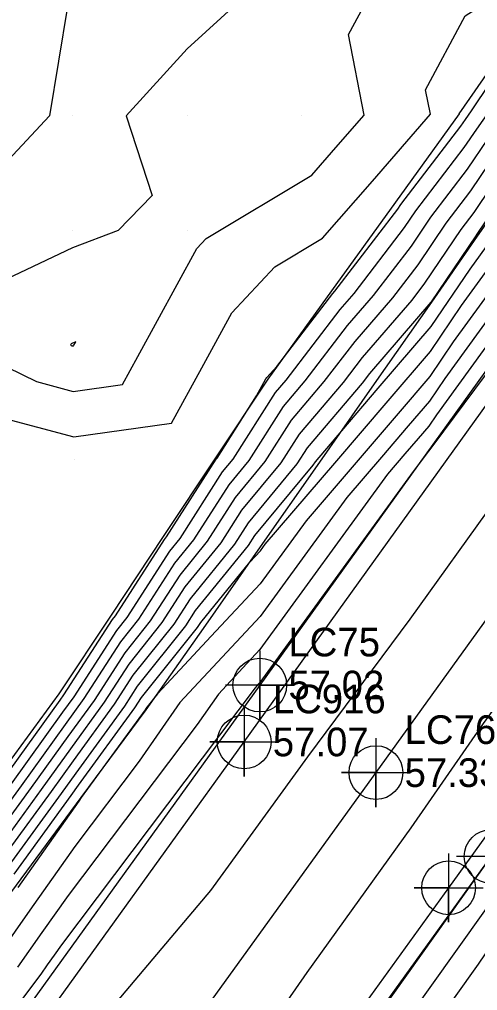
# Model space of a CAD drawing. Extents: x 2188792 to 2191981, y 386090 to 389710.
# Drawn here: x 2189815.5 to 2189855.4, y 387193.8 to 387278.5 of the extents above; entities that cross this region are included whole.
import ezdxf

# ---------------------------------------------------------------- set-up
doc = ezdxf.new("R2010")
doc.units = 0
for name, color, linetype in [('DTM Contours Major', 7, 'Continuous'), ('DTM Contours Minor', 7, 'Continuous'), ('Exist DTM QL2 LIDAR Elevation Point', 7, 'Continuous'), ('Exist Roads EOP', 7, 'Continuous'), ('Exist Roads EOP Cogo Elevation', 7, 'Continuous'), ('Exist Roads EOP Cogo Number', 7, 'Continuous'), ('Exist Roads EOP Cogo Point CELL', 7, 'Continuous'), ('Exist Roads EOT', 7, 'Continuous'), ('Exist Roads EOT Cogo Elevation', 7, 'Continuous'), ('Exist Roads EOT Cogo Number', 7, 'Continuous'), ('Exist Roads EOT Cogo Point CELL', 7, 'Continuous'), ('PH Exist DTM Breakline', 7, 'Continuous')]:
    doc.layers.add(name, color=color, linetype=linetype)

msp = doc.modelspace()

# ---------------------------------------------------------------- linework, layer by layer
at = {"layer": 'DTM Contours Major'}
for points in [[(2189839.476, 387181.412), (2189856.598, 387205.434), (2189856.62, 387205.466), (2189856.64, 387205.496), (2189856.659, 387205.525), (2189858.223, 387207.732), (2189869.834, 387224.619), (2189877.249, 387235.156), (2189886.017, 387247.794), (2189890.656, 387253.898), (2189892.445, 387256.247), (2189909.424, 387278.537), (2189910.292, 387279.677), (2189910.315, 387279.709), (2189911.35, 387281.066), (2189927.816, 387303.457), (2189927.931, 387303.631), (2189928.041, 387303.798), (2189928.147, 387303.957), (2189928.3, 387304.131), (2189939.5, 387319.43), (2189939.713, 387319.861), (2189939.829, 387320.314), (2189949.954, 387334.279)], [(2189889.131, 387294.16), (2189875.837, 387275.244), (2189873.402, 387271.521), (2189871.117, 387268.163), (2189868.023, 387263.523), (2189851.528, 387241.376), (2189851.153, 387240.864), (2189849.827, 387239.091), (2189836.429, 387220.687), (2189836.321, 387220.571), (2189836.166, 387220.405), (2189836.033, 387220.214), (2189819.116, 387197.803), (2189818.476, 387196.893), (2189817.877, 387196.042), (2189817.316, 387195.246), (2189805.405, 387179.378)], [(2189814.781, 387205.028), (2189819.114, 387210.993), (2189820.392, 387212.776), (2189824.645, 387218.631), (2189825.754, 387220.352), (2189829.968, 387225.621), (2189830.826, 387226.958), (2189835.436, 387232.628), (2189835.992, 387233.498), (2189841.102, 387239.658), (2189841.287, 387239.949), (2189843.591, 387242.658), (2189846.764, 387246.355), (2189851.385, 387251.738), (2189854.777, 387256.754), (2189857.49, 387260.492), (2189860.766, 387265.355), (2189865.205, 387271.534), (2189865.782, 387272.354), (2189870.049, 387278.295), (2189874.071, 387283.895)], [(2189814.771, 387211.853), (2189819.239, 387218.082), (2189820.225, 387219.44), (2189823.946, 387225.213), (2189824.855, 387226.349), (2189828.568, 387232.132), (2189829.484, 387233.259), (2189833.187, 387239.053), (2189834.112, 387240.169), (2189837.802, 387245.976), (2189838.739, 387247.078), (2189843.449, 387253.234), (2189844.661, 387254.641), (2189849.066, 387260.374), (2189850.055, 387261.845), (2189854.272, 387267.354), (2189855.357, 387268.963), (2189856.833, 387271.018), (2189860.8, 387276.948), (2189862.222, 387278.923)]]:
    msp.add_lwpolyline(points, dxfattribs=at)
at = {"layer": 'DTM Contours Minor'}
for points in [[(2189806.103, 387171.079), (2189818.83, 387185.769), (2189823.977, 387192.841), (2189832.146, 387202.524), (2189840.636, 387214.199), (2189849.542, 387226.21), (2189857.019, 387236.627), (2189863.862, 387245.866), (2189872.906, 387258.466), (2189874.441, 387260.833), (2189883.298, 387274.48), (2189889.961, 387284.755), (2189894.836, 387292.266), (2189899.699, 387299.764), (2189911.601, 387317.434), (2189912.049, 387318.099), (2189914.929, 387322.013), (2189928.336, 387339.246)], [(2189813.858, 387243.807), (2189820.216, 387242.114), (2189828.739, 387243.302), (2189831.378, 387248.153), (2189833.988, 387252.937), (2189837.728, 387256.941), (2189841.913, 387259.442), (2189846.252, 387264.442), (2189851.314, 387270.276), (2189850.901, 387272.402), (2189854.354, 387278.869), (2189857.509, 387280.879), (2189861.388, 387287.422), (2189863.782, 387290.182), (2189867.521, 387296.313), (2189870.901, 387301.854), (2189870.566, 387305.397), (2189874.896, 387306.987), (2189878.866, 387313.349), (2189882.188, 387319.115), (2189885.105, 387322.219), (2189888.384, 387327.734)], [(2189830.091, 387327.202), (2189821.116, 387320.135), (2189820.905, 387319.321), (2189820.191, 387310.134), (2189827.038, 387307.081), (2189829.651, 387300.133), (2189830.091, 387297.292), (2189831.409, 387290.132), (2189830.091, 387286.609), (2189826.983, 387283.24), (2189820.09, 387280.72), (2189818.925, 387281.297), (2189817.626, 387280.131), (2189819.642, 387279.683), (2189818.075, 387270.13), (2189810.09, 387261.582)], [(2189937.835, 387325.802), (2189928.451, 387313.821), (2189924.705, 387308.455), (2189912.794, 387292.052), (2189906.641, 387284.303), (2189906.065, 387283.51), (2189895.672, 387270.72), (2189887.112, 387259.916), (2189885.216, 387257.522), (2189881.384, 387252.787), (2189871.553, 387239.191), (2189863.95, 387228.232), (2189855.914, 387217.121), (2189849.603, 387208.007), (2189840.533, 387195.387), (2189832.223, 387183.387), (2189825.819, 387174.474), (2189818.869, 387164.423), (2189809.4, 387152.406)], [(2189810.442, 387250.128), (2189816.943, 387246.936), (2189820.154, 387246.081), (2189824.458, 387246.681), (2189825.791, 387249.131), (2189830.938, 387258.566), (2189831.751, 387259.436), (2189840.975, 387264.949), (2189843.078, 387267.373), (2189845.532, 387270.201), (2189844.168, 387277.217), (2189845.47, 387279.656), (2189854.089, 387285.146), (2189856.18, 387288.672), (2189861.898, 387295.265), (2189863.728, 387298.264), (2189865.381, 387300.975), (2189864.714, 387308.045), (2189873.352, 387311.215), (2189876.045, 387315.531), (2189878.299, 387319.443), (2189883.416, 387324.889)], [(2189855.326, 387325.368), (2189854.148, 387320.135), (2189852.181, 387312.222), (2189854.893, 387310.134), (2189854.413, 387305.814), (2189850.093, 387306.667), (2189846.951, 387300.133), (2189847.286, 387292.939), (2189840.092, 387292.165), (2189835.482, 387294.742), (2189836.331, 387290.132), (2189834.084, 387284.123), (2189834.654, 387280.131), (2189830.091, 387275.989), (2189824.774, 387270.13), (2189827.041, 387263.18), (2189824.072, 387260.129), (2189820.09, 387258.603), (2189814.336, 387255.883)], [(2189849.089, 387187.083), (2189855.514, 387196.097), (2189858.561, 387200.607), (2189861.481, 387204.929), (2189864.282, 387209.076), (2189870.405, 387217.719), (2189872.925, 387221.801), (2189874.972, 387225.117), (2189876.668, 387227.865), (2189886.895, 387242.237), (2189888.817, 387245.23), (2189890.642, 387248.071), (2189892.222, 387250.529), (2189894.767, 387253.972), (2189896.249, 387256.263), (2189897.556, 387258.284), (2189910.059, 387275.238), (2189911.623, 387277.599), (2189913.027, 387279.718), (2189914.163, 387281.453), (2189926.879, 387298.745), (2189928.163, 387300.687), (2189929.39, 387302.543), (2189930.564, 387304.318)], [(2189886.854, 387293.151), (2189872.459, 387272.671), (2189871.692, 387271.603), (2189870.878, 387270.469), (2189868.011, 387266.389), (2189867.203, 387265.264), (2189866.606, 387264.378), (2189851.846, 387244.042), (2189851.172, 387243.045), (2189850.253, 387241.975), (2189849.094, 387240.624), (2189847.585, 387238.866), (2189836.443, 387223.561), (2189834.943, 387221.952), (2189832.814, 387219.669), (2189830.965, 387217.02), (2189819.697, 387202.092), (2189817.42, 387198.857), (2189815.292, 387195.834)], [(2189884.576, 387292.143), (2189872.862, 387275.477), (2189871.281, 387273.276), (2189869.604, 387270.941), (2189867.31, 387267.675), (2189865.594, 387265.286), (2189864.327, 387263.407), (2189852.579, 387247.22), (2189851.225, 387245.219), (2189849.381, 387243.07), (2189847.054, 387240.358), (2189844.024, 387236.829), (2189836.458, 387226.435), (2189833.566, 387223.334), (2189829.461, 387218.933), (2189825.898, 387213.827), (2189820.277, 387206.38), (2189816.364, 387200.821), (2189812.707, 387195.626)], [(2189882.298, 387291.135), (2189873.265, 387278.283), (2189870.87, 387274.949), (2189868.33, 387271.412), (2189866.608, 387268.961), (2189863.984, 387265.309), (2189862.048, 387262.435), (2189853.312, 387250.398), (2189851.278, 387247.392), (2189848.509, 387244.165), (2189845.013, 387240.093), (2189840.463, 387234.791), (2189836.472, 387229.308), (2189832.189, 387224.716), (2189827.515, 387219.705), (2189826.478, 387218.408), (2189826.413, 387218.308), (2189820.854, 387210.653), (2189820.851, 387210.649), (2189820.628, 387210.343), (2189815.308, 387202.785)], [(2189814.996, 387203.957), (2189819.982, 387210.821), (2189820.623, 387211.715), (2189825.529, 387218.469), (2189826.116, 387219.38), (2189830.99, 387225.475), (2189831.278, 387225.923), (2189835.553, 387231.182), (2189836.486, 387232.182), (2189836.902, 387232.753), (2189842.973, 387239.827), (2189847.637, 387245.26), (2189851.331, 387249.565), (2189854.044, 387253.576), (2189859.769, 387261.463), (2189862.375, 387265.332), (2189865.907, 387270.247), (2189867.056, 387271.883), (2189870.46, 387276.622), (2189873.668, 387281.089)], [(2189814.349, 387207.169), (2189817.377, 387211.337), (2189819.931, 387214.898), (2189822.877, 387218.955), (2189825.031, 387222.296), (2189827.923, 387225.912), (2189829.923, 387229.028), (2189833.055, 387232.88), (2189834.87, 387235.72), (2189838.306, 387239.862), (2189839.893, 387242.36), (2189843.723, 387246.863), (2189845.39, 387249.042), (2189849.713, 387254.058), (2189850.833, 387255.517), (2189853.994, 387260.214), (2189855.125, 387261.692), (2189858.289, 387266.384), (2189862.592, 387272.379), (2189863.579, 387273.853), (2189867.998, 387279.994)], [(2189814.565, 387206.098), (2189818.245, 387211.165), (2189820.162, 387213.837), (2189823.761, 387218.793), (2189825.393, 387221.324), (2189828.945, 387225.767), (2189830.374, 387227.993), (2189834.246, 387232.754), (2189835.431, 387234.609), (2189839.704, 387239.76), (2189840.59, 387241.154), (2189845.384, 387246.791), (2189846.037, 387247.645), (2189851.396, 387253.864), (2189851.422, 387253.898), (2189855.307, 387259.671), (2189855.409, 387259.804), (2189859.267, 387265.524), (2189864.306, 387272.545), (2189864.504, 387272.82), (2189864.508, 387272.826), (2189869.638, 387279.969)], [(2189813.917, 387209.31), (2189815.639, 387211.681), (2189819.469, 387217.021), (2189821.109, 387219.278), (2189824.308, 387224.241), (2189825.878, 387226.204), (2189829.02, 387231.097), (2189830.675, 387233.133), (2189833.748, 387237.942), (2189835.51, 387240.066), (2189838.499, 387244.771), (2189840.4, 387247.006), (2189844.096, 387251.837), (2189846.345, 387254.447), (2189849.655, 387258.755), (2189851.368, 387261.301), (2189854.556, 387265.467), (2189856.335, 387268.103), (2189858.752, 387271.472), (2189861.727, 387275.916), (2189864.147, 387279.28)], [(2189814.133, 387208.239), (2189816.508, 387211.509), (2189819.7, 387215.959), (2189821.993, 387219.116), (2189824.669, 387223.269), (2189826.9, 387226.058), (2189829.471, 387230.062), (2189831.865, 387233.007), (2189834.309, 387236.831), (2189836.908, 387239.964), (2189839.196, 387243.565), (2189842.061, 387246.935), (2189844.743, 387250.439), (2189848.029, 387254.252), (2189850.244, 387257.136), (2189852.681, 387260.758), (2189854.84, 387263.579), (2189857.312, 387267.243), (2189860.672, 387271.925), (2189862.653, 387274.885), (2189866.072, 387279.637)], [(2189813.902, 387212.025), (2189819.008, 387219.143), (2189819.341, 387219.602), (2189823.585, 387226.185), (2189823.832, 387226.495), (2189828.116, 387233.167), (2189828.294, 387233.385), (2189832.626, 387240.164), (2189832.714, 387240.271), (2189836.156, 387245.688), (2189836.965, 387247.175), (2189837.038, 387247.308), (2189837.929, 387248.262), (2189842.802, 387254.631), (2189842.978, 387254.835), (2189848.476, 387261.993), (2189848.742, 387262.388), (2189853.988, 387269.242), (2189854.38, 387269.823), (2189854.913, 387270.565), (2189859.874, 387277.98), (2189860.296, 387278.567)], [(2189844.282, 387184.248), (2189856.056, 387200.766), (2189857.59, 387203.036), (2189859.06, 387205.212), (2189860.471, 387207.3), (2189870.937, 387222.073), (2189872.12, 387223.99), (2189873.082, 387225.548), (2189873.878, 387226.839), (2189888.114, 387246.845), (2189888.927, 387248.111), (2189889.699, 387249.313), (2189890.368, 387250.353), (2189893.609, 387254.737), (2189894.257, 387255.739), (2189894.829, 387256.623), (2189910.184, 387277.446), (2189910.961, 387278.619)], [(2189820.363, 387250.401), (2189820.09, 387250.297), (2189819.976, 387250.243), (2189819.899, 387250.128), (2189820.028, 387250.065), (2189820.092, 387250.048), (2189820.177, 387250.06), (2189820.204, 387250.109), (2189820.363, 387250.401)]]:
    msp.add_lwpolyline(points, dxfattribs=at)
at = {"layer": 'Exist DTM QL2 LIDAR Elevation Point'}
for p, q in [((2189820.09, 387270.13), (2189820.09, 387270.13)), ((2189830.091, 387270.13), (2189830.091, 387270.13)), ((2189840.092, 387270.13), (2189840.092, 387270.13)), ((2189820.09, 387260.129), (2189820.09, 387260.129)), ((2189830.091, 387260.129), (2189830.091, 387260.129)), ((2189820.09, 387250.128), (2189820.09, 387250.128)), ((2189820.247, 387240.144), (2189820.247, 387240.144))]:
    msp.add_line(p, q, dxfattribs=at)
at = {"layer": 'Exist Roads EOP'}
for points in [[(2190313.986, 387884.141), (2190285.547, 387843.636), (2190254.588, 387800.045), (2190225.155, 387759.32), (2190194.829, 387717.425), (2190164.291, 387675.101), (2190137.229, 387637.301), (2190105.098, 387592.774), (2190071.411, 387546.221), (2190039.296, 387501.568), (2190007.542, 387457.958), (2189976.844, 387415.407), (2189936.359, 387359.145), (2189907.138, 387318.716), (2189868.636, 387265.243), (2189836.428, 387220.463), (2189805.695, 387177.815), (2189775.592, 387135.957), (2189745.498, 387094.055), (2189715.496, 387052.249), (2189683.869, 387008.07), (2189653.218, 386965.867), (2189623.729, 386924.667)], [(2190335.128, 387868.989), (2190306.373, 387829.271), (2190274.581, 387784.921), (2190245.133, 387744.071), (2190214.553, 387701.741), (2190184.89, 387660.475), (2190157.493, 387622.204), (2190126.048, 387578.501), (2190091.216, 387530.568), (2190059.634, 387486.726), (2190026.932, 387441.783), (2189997.689, 387401.032), (2189957.023, 387344.154), (2189927.908, 387303.922), (2189889.008, 387250.224), (2189856.606, 387205.5), (2189825.68, 387162.612), (2189795.668, 387120.822), (2189765.955, 387079.619), (2189734.998, 387036.704), (2189703.849, 386993.356), (2189673.984, 386951.979), (2189643.253, 386909.427)]]:
    msp.add_lwpolyline(points, dxfattribs=at)
at = {"layer": 'Exist Roads EOP Cogo Point CELL'}
for points in [[(2189836.428, 387223.463), (2189836.428, 387217.463), (2189836.428, 387220.463), (2189839.428, 387220.463), (2189833.428, 387220.463)], [(2189856.606, 387208.5), (2189856.606, 387202.5), (2189856.606, 387205.5), (2189859.606, 387205.5), (2189853.606, 387205.5)]]:
    msp.add_lwpolyline(points, dxfattribs=at)
for centre in [(2189836.428, 387220.463), (2189856.606, 387205.5)]:
    msp.add_circle(centre, 2.344, dxfattribs=at)
at = {"layer": 'Exist Roads EOT'}
for points in [[(2190174.375, 387667.889), (2190147.471, 387630.495), (2190115.247, 387585.778), (2190081.202, 387538.232), (2190049.502, 387494.256), (2190017.538, 387450.182), (2189987.334, 387408.357), (2189946.666, 387352.019), (2189917.402, 387311.129), (2189878.955, 387257.772), (2189846.565, 387212.819), (2189815.837, 387170.306), (2189785.374, 387128.351), (2189755.717, 387086.921), (2189724.953, 387044.041), (2189693.727, 387000.805), (2189663.933, 386959.217), (2189633.425, 386917.196)], [(2189989.253, 387391.986), (2189958.581, 387349.453), (2189928.09, 387307.216), (2189909.67, 387281.603), (2189884.44, 387246.513), (2189852.91, 387202.766), (2189821.507, 387159.305), (2189790.01, 387115.85), (2189759.16, 387072.957), (2189728.247, 387029.91), (2189696.407, 386985.689), (2189665.45, 386942.736), (2189635.049, 386900.502)], [(2189619.904, 386917.168), (2189650.19, 386959.038), (2189680.959, 387001.734), (2189713.171, 387046.57), (2189739.87, 387083.883), (2189771.556, 387127.847), (2189803.188, 387171.311), (2189835.065, 387215.496), (2189866.485, 387259.202), (2189892.308, 387295.019), (2189910.407, 387320.236), (2189942.075, 387364.22)]]:
    msp.add_lwpolyline(points, dxfattribs=at)
at = {"layer": 'Exist Roads EOT Cogo Point CELL'}
for points in [[(2189835.065, 387218.496), (2189835.065, 387212.496), (2189835.065, 387215.496), (2189832.065, 387215.496), (2189838.065, 387215.496)], [(2189846.565, 387215.819), (2189846.565, 387209.819), (2189846.565, 387212.819), (2189843.565, 387212.819), (2189849.565, 387212.819)], [(2189852.91, 387205.766), (2189852.91, 387199.766), (2189852.91, 387202.766), (2189849.91, 387202.766), (2189855.91, 387202.766)]]:
    msp.add_lwpolyline(points, dxfattribs=at)
for centre in [(2189835.065, 387215.496), (2189846.565, 387212.819), (2189852.91, 387202.766)]:
    msp.add_circle(centre, 2.344, dxfattribs=at)
at = {"layer": 'PH Exist DTM Breakline'}
for points in [[(2189853.827, 387270.309), (2189859.482, 387278.416), (2189865.137, 387286.523), (2189870.792, 387294.63), (2189876.447, 387302.737), (2189882.103, 387310.844), (2189887.345, 387318.68), (2189892.587, 387326.516)], [(2189853.827, 387270.309), (2189848.26, 387262.588), (2189842.692, 387254.868), (2189837.125, 387247.147), (2189832.566, 387240.282), (2189828.008, 387233.416), (2189823.449, 387226.55), (2189818.89, 387219.684), (2189813.347, 387212.135)], [(2189755.77, 387138.982), (2189763.02, 387141.08), (2189767.474, 387144.445), (2189776.546, 387153.145), (2189781.956, 387159.882), (2189787.366, 387166.618), (2189792.776, 387173.355), (2189798.186, 387180.091), (2189803.853, 387187.73), (2189809.52, 387195.37), (2189815.188, 387203.009), (2189820.855, 387210.648), (2189826.522, 387218.288), (2189831.505, 387225.402), (2189836.488, 387232.516), (2189841.471, 387239.631), (2189846.454, 387246.745), (2189851.437, 387253.86), (2189855.437, 387259.617), (2189859.437, 387265.374)]]:
    msp.add_lwpolyline(points, dxfattribs=at)

# ---------------------------------------------------------------- texts
at = {"layer": 'Exist Roads EOP Cogo Elevation'}
msp.add_text('57.02', height=2.5, dxfattribs=at).set_placement((2189838.928, 387219.213))
at = {"layer": 'Exist Roads EOP Cogo Number'}
msp.add_text('LC75', height=2.5, dxfattribs=at).set_placement((2189838.928, 387222.963))
at = {"layer": 'Exist Roads EOT Cogo Elevation'}
for s, p in [('57.07', (2189837.565, 387214.246)), ('57.33', (2189849.065, 387211.569))]:
    msp.add_text(s, height=2.5, dxfattribs=at).set_placement(p)
at = {"layer": 'Exist Roads EOT Cogo Number'}
for s, p in [('LC916', (2189837.565, 387217.996)), ('LC76', (2189849.065, 387215.319))]:
    msp.add_text(s, height=2.5, dxfattribs=at).set_placement(p)

doc.saveas('drawing.dxf')
